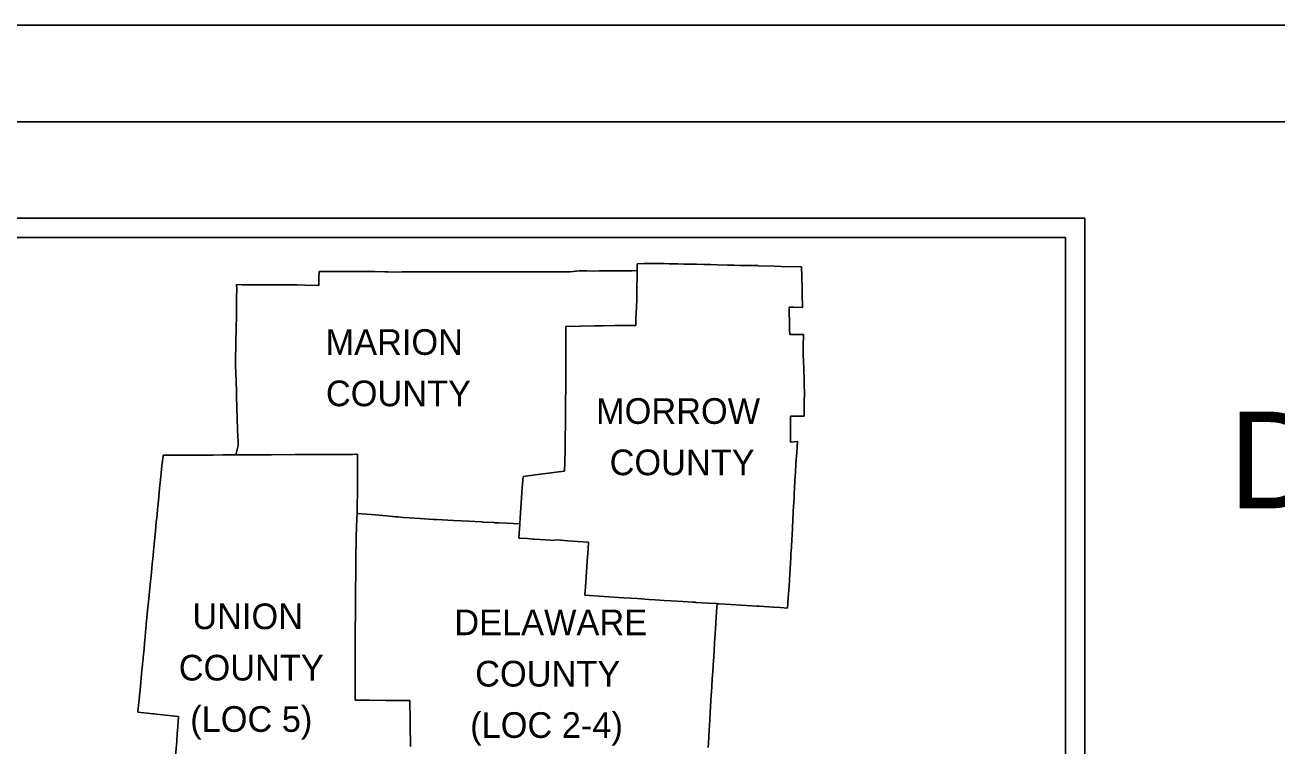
# Model space of a CAD drawing. Extents: x 0 to 34, y 0 to 22.
# Drawn here: x 3.52 to 9.99, y 18.27 to 22 of the extents above; entities that cross this region are included whole.
import ezdxf

# ---------------------------------------------------------------- set-up
doc = ezdxf.new("R2010")
doc.units = 0
for name, color, linetype in [('GM_X_County', 7, 'Continuous'), ('SH_Border', 7, 'Continuous'), ('SH_Cut_Line', 7, 'Continuous'), ('SH_Data', 7, 'Continuous'), ('SH_Text', 7, 'Continuous')]:
    doc.layers.add(name, color=color, linetype=linetype)

msp = doc.modelspace()

# ---------------------------------------------------------------- linework, layer by layer
at = {"layer": 'GM_X_County'}
for p, q in [((5.0405, 20.6879), (5.0411, 20.725)), ((5.0411, 20.725), (5.0621, 20.7251)), ((5.0621, 20.7251), (5.1848, 20.725)), ((5.1848, 20.725), (5.2501, 20.7247)), ((5.2501, 20.7247), (5.329, 20.7243)), ((5.329, 20.7243), (5.3818, 20.7231)), ((5.3818, 20.7231), (5.3901, 20.7232)), ((5.3901, 20.7232), (5.3993, 20.723)), ((5.3993, 20.723), (5.4521, 20.7223)), ((5.4521, 20.7223), (5.4693, 20.7224)), ((5.4693, 20.7224), (5.5416, 20.7227)), ((5.5416, 20.7227), (5.567, 20.7229)), ((5.567, 20.7229), (5.5697, 20.723)), ((5.5697, 20.723), (5.5794, 20.7231)), ((5.5794, 20.7231), (5.6115, 20.7233)), ((5.6115, 20.7233), (5.6401, 20.7234)), ((5.6401, 20.7234), (5.6827, 20.7237)), ((5.6827, 20.7237), (5.753, 20.724)), ((5.753, 20.724), (5.8235, 20.7233)), ((5.8235, 20.7233), (5.8261, 20.7233)), ((5.8261, 20.7233), (5.8298, 20.7232)), ((5.8298, 20.7232), (5.8419, 20.7232)), ((5.8419, 20.7232), (5.8941, 20.7231)), ((5.8941, 20.7231), (5.9122, 20.7229)), ((5.9122, 20.7229), (6.0406, 20.7231)), ((6.0406, 20.7231), (6.1476, 20.7233)), ((6.1476, 20.7233), (6.2484, 20.7238)), ((6.2484, 20.7238), (6.2963, 20.723)), ((6.2963, 20.723), (6.3143, 20.7226)), ((6.3143, 20.7226), (6.3191, 20.7226)), ((6.3191, 20.7226), (6.3236, 20.7228)), ((6.3236, 20.7228), (6.3375, 20.7237)), ((6.3375, 20.7237), (6.3545, 20.725)), ((6.3545, 20.725), (6.3662, 20.7259)), ((6.3662, 20.7259), (6.3728, 20.7263)), ((6.3728, 20.7263), (6.3872, 20.7275)), ((6.3872, 20.7275), (6.3891, 20.7276)), ((6.3891, 20.7276), (6.4254, 20.7277)), ((6.4254, 20.7277), (6.4621, 20.7274)), ((6.4621, 20.7274), (6.4892, 20.7279)), ((6.4892, 20.7279), (6.4913, 20.728)), ((6.4913, 20.728), (6.4973, 20.728)), ((6.4973, 20.728), (6.5516, 20.7282)), ((6.5516, 20.7282), (6.5752, 20.7283)), ((6.5752, 20.7283), (6.6354, 20.7289)), ((6.6354, 20.7289), (6.6595, 20.7292)), ((6.6595, 20.7292), (6.6856, 20.7295)), ((6.6856, 20.7295), (6.6853, 20.6951)), ((6.6856, 20.7295), (6.6866, 20.7654)), ((6.6866, 20.7654), (6.7195, 20.7656)), ((6.7195, 20.7656), (6.7729, 20.7658)), ((6.7729, 20.7658), (6.7945, 20.7658)), ((6.7945, 20.7658), (6.803, 20.7656)), ((6.803, 20.7656), (6.8079, 20.7658)), ((6.8079, 20.7658), (6.8254, 20.766)), ((6.8254, 20.766), (6.8515, 20.7651)), ((6.8515, 20.7651), (6.886, 20.7639)), ((6.886, 20.7639), (6.8953, 20.7638)), ((6.8953, 20.7638), (6.9269, 20.7633)), ((6.9269, 20.7633), (6.9307, 20.7631)), ((6.9307, 20.7631), (6.9473, 20.7629)), ((6.9473, 20.7629), (6.9532, 20.7628)), ((6.9532, 20.7628), (6.9634, 20.7628)), ((6.9634, 20.7628), (6.9922, 20.7622)), ((6.9922, 20.7622), (7.0299, 20.7614)), ((7.0299, 20.7614), (7.0649, 20.7604)), ((7.0649, 20.7604), (7.1, 20.7596)), ((7.1, 20.7596), (7.1524, 20.7582)), ((7.1524, 20.7582), (7.1695, 20.7575)), ((7.1695, 20.7575), (7.1866, 20.7571)), ((7.1866, 20.7571), (7.2147, 20.7565)), ((7.2147, 20.7565), (7.3093, 20.7565)), ((7.3093, 20.7565), (7.3093, 20.7542)), ((7.3093, 20.7542), (7.3951, 20.752)), ((7.3951, 20.752), (7.4302, 20.7511)), ((7.4302, 20.7511), (7.5362, 20.7483)), ((7.5362, 20.7483), (7.5371, 20.6992)), ((4.6151, 20.6558), (4.6152, 20.6569)), ((4.6151, 20.652), (4.6151, 20.6558)), ((4.6153, 20.6358), (4.6151, 20.652)), ((4.6152, 20.6569), (4.6438, 20.6567)), ((4.6438, 20.6567), (4.7179, 20.6562)), ((4.7179, 20.6562), (4.7573, 20.656)), ((4.7573, 20.656), (4.8279, 20.656)), ((4.8279, 20.656), (4.899, 20.6556)), ((4.899, 20.6556), (4.9257, 20.6554)), ((4.9257, 20.6554), (4.9685, 20.6545)), ((4.9685, 20.6545), (5.0394, 20.6529)), ((5.0394, 20.6529), (5.04, 20.6529)), ((5.04, 20.6537), (5.0405, 20.6879)), ((5.04, 20.6529), (5.04, 20.6537)), ((6.6853, 20.6951), (6.6847, 20.6432)), ((7.5371, 20.6992), (7.5389, 20.6325)), ((4.6149, 20.534), (4.6152, 20.5873)), ((4.6152, 20.5873), (4.6153, 20.6358)), ((6.6841, 20.5823), (6.6829, 20.5394)), ((6.6845, 20.6263), (6.6841, 20.5852)), ((6.6841, 20.5852), (6.6841, 20.5823)), ((6.6847, 20.6432), (6.6845, 20.6263)), ((7.5389, 20.6325), (7.5396, 20.6085)), ((7.5396, 20.6085), (7.5412, 20.5388)), ((4.6142, 20.4815), (4.6149, 20.534)), ((6.6828, 20.5379), (6.6796, 20.4842)), ((6.6829, 20.5394), (6.6828, 20.5379)), ((7.4947, 20.5397), (7.4719, 20.5401)), ((7.4719, 20.5401), (7.4724, 20.5242)), ((7.4724, 20.5242), (7.4722, 20.5102)), ((7.5412, 20.5388), (7.4947, 20.5397)), ((4.6134, 20.4465), (4.6142, 20.4815)), ((6.6796, 20.4842), (6.6794, 20.4454)), ((7.4722, 20.5102), (7.4722, 20.5091)), ((7.4722, 20.5091), (7.4731, 20.4672)), ((7.4731, 20.4672), (7.474, 20.4249)), ((4.6106, 20.3414), (4.6134, 20.4465)), ((6.3888, 20.4424), (6.3171, 20.441)), ((6.3171, 20.441), (6.3172, 20.4059)), ((6.3172, 20.4059), (6.3172, 20.3947)), ((6.3172, 20.3947), (6.3173, 20.3712)), ((6.3927, 20.4425), (6.3888, 20.4424)), ((6.4647, 20.4432), (6.3927, 20.4425)), ((6.4769, 20.4434), (6.4647, 20.4432)), ((6.482, 20.4435), (6.4769, 20.4434)), ((6.5063, 20.444), (6.482, 20.4435)), ((6.5685, 20.4447), (6.5063, 20.444)), ((6.603, 20.4451), (6.5685, 20.4447)), ((6.6383, 20.4454), (6.603, 20.4451)), ((6.6794, 20.4454), (6.6383, 20.4454)), ((7.474, 20.4249), (7.4745, 20.3989)), ((7.4745, 20.3989), (7.4952, 20.3991)), ((7.4952, 20.3991), (7.5454, 20.3989)), ((7.5454, 20.3989), (7.5444, 20.3365)), ((4.6101, 20.2718), (4.6106, 20.3414)), ((6.3173, 20.3435), (6.3172, 20.2998)), ((6.3173, 20.3712), (6.3173, 20.3435)), ((7.5444, 20.3365), (7.5443, 20.3345)), ((7.5443, 20.3345), (7.5443, 20.3204)), ((4.61, 20.2358), (4.6101, 20.2708)), ((4.6101, 20.2708), (4.6101, 20.2718)), ((6.3172, 20.2998), (6.317, 20.2299)), ((7.5443, 20.3204), (7.5444, 20.2979)), ((7.5444, 20.2979), (7.5459, 20.2576)), ((4.6104, 20.2048), (4.61, 20.2358)), ((4.6137, 20.1056), (4.6104, 20.2048)), ((6.317, 20.2299), (6.3168, 20.1568)), ((7.5459, 20.2576), (7.5473, 20.2239)), ((7.5473, 20.2239), (7.5487, 20.1629)), ((6.3168, 20.1568), (6.3153, 20.0187)), ((7.5487, 20.1629), (7.549, 20.153)), ((7.549, 20.153), (7.5507, 20.0826)), ((4.6143, 20.0864), (4.6137, 20.1056)), ((4.6146, 20.0742), (4.6143, 20.0864)), ((4.6147, 20.073), (4.6146, 20.0742)), ((4.6159, 20.0266), (4.6147, 20.073)), ((7.5499, 20.0717), (7.5496, 20.0678)), ((7.5496, 20.0678), (7.5496, 20.0631)), ((7.55, 20.0727), (7.5499, 20.0717)), ((7.5503, 20.0735), (7.55, 20.0727)), ((7.5506, 20.074), (7.5503, 20.0735)), ((7.5508, 20.079), (7.5506, 20.074)), ((7.5507, 20.0826), (7.5508, 20.079)), ((4.616, 20.0228), (4.6159, 20.0266)), ((4.6162, 20.0178), (4.616, 20.0228)), ((4.6179, 19.9678), (4.6162, 20.0178)), ((6.3153, 20.0187), (6.3146, 19.9478)), ((7.5496, 20.0597), (7.5495, 20.0116)), ((7.5495, 20.0116), (7.5497, 19.9808)), ((7.5496, 20.0631), (7.5496, 20.0597)), ((4.6203, 19.902), (4.6179, 19.9678)), ((6.3146, 19.9478), (6.3135, 19.8521)), ((7.4791, 19.945), (7.479, 19.9046)), ((7.5453, 19.9759), (7.4791, 19.9766)), ((7.4791, 19.9766), (7.4791, 19.9708)), ((7.4791, 19.9708), (7.4791, 19.945)), ((7.5497, 19.9759), (7.5453, 19.9759)), ((7.5497, 19.9808), (7.5497, 19.9759)), ((4.6225, 19.8473), (4.6203, 19.902)), ((7.479, 19.9046), (7.4788, 19.8413)), ((4.6114, 19.7761), (4.6234, 19.8253)), ((4.6234, 19.8253), (4.6225, 19.8473)), ((6.3128, 19.8072), (6.3116, 19.737)), ((6.3135, 19.8521), (6.3128, 19.8072)), ((7.4788, 19.8413), (7.5127, 19.8457)), ((7.5145, 19.8458), (7.5105, 19.7867)), ((7.5127, 19.8457), (7.5145, 19.8458)), ((4.2291, 19.7189), (4.2348, 19.7709)), ((4.2348, 19.7709), (4.2352, 19.7745)), ((4.2352, 19.7745), (4.2355, 19.7745)), ((4.2355, 19.7745), (4.3101, 19.7744)), ((4.3101, 19.7744), (4.3201, 19.7745)), ((4.3201, 19.7745), (4.4466, 19.7751)), ((4.4466, 19.7751), (4.4939, 19.7753)), ((4.4939, 19.7753), (4.5443, 19.7756)), ((4.5443, 19.7756), (4.6114, 19.7761)), ((4.6572, 19.7763), (4.6114, 19.7761)), ((4.7464, 19.7766), (4.6572, 19.7763)), ((4.7722, 19.7767), (4.7464, 19.7766)), ((4.7947, 19.7769), (4.7722, 19.7767)), ((4.9158, 19.7778), (4.7947, 19.7769)), ((4.9688, 19.778), (4.9158, 19.7778)), ((5.0125, 19.7781), (4.9688, 19.778)), ((5.085, 19.7785), (5.0125, 19.7781)), ((5.1554, 19.7788), (5.085, 19.7785)), ((5.2154, 19.779), (5.1554, 19.7788)), ((5.2346, 19.7791), (5.2154, 19.779)), ((5.2402, 19.7791), (5.2346, 19.7791)), ((5.2403, 19.7489), (5.2402, 19.7791)), ((5.2402, 19.7186), (5.2403, 19.7452)), ((5.2403, 19.7452), (5.2403, 19.7489)), ((7.5105, 19.7867), (7.5068, 19.7342)), ((4.2193, 19.6292), (4.2291, 19.7189)), ((5.2399, 19.6563), (5.2402, 19.7186)), ((6.2406, 19.6837), (6.1578, 19.6725)), ((6.2538, 19.6854), (6.2406, 19.6837)), ((6.2938, 19.6906), (6.2538, 19.6854)), ((6.3106, 19.6928), (6.2938, 19.6906)), ((6.3116, 19.737), (6.3106, 19.6928)), ((7.5038, 19.6809), (7.503, 19.6673)), ((7.5047, 19.697), (7.5038, 19.6809)), ((7.5059, 19.7185), (7.5047, 19.697)), ((7.5068, 19.7342), (7.5059, 19.7185)), ((4.2107, 19.5404), (4.2184, 19.6213)), ((4.2184, 19.6213), (4.2193, 19.6292)), ((5.2392, 19.5669), (5.2396, 19.6128)), ((5.2396, 19.6128), (5.2399, 19.6563)), ((6.0957, 19.6636), (6.0918, 19.6072)), ((6.1326, 19.6689), (6.0957, 19.6636)), ((6.1384, 19.6697), (6.1326, 19.6689)), ((6.1578, 19.6725), (6.1384, 19.6697)), ((7.503, 19.6673), (7.4982, 19.5761)), ((5.2387, 19.5275), (5.2392, 19.5669)), ((6.0918, 19.6072), (6.0864, 19.5285)), ((7.4968, 19.5568), (7.4952, 19.5252)), ((7.4982, 19.5761), (7.4968, 19.5568)), ((4.2036, 19.4675), (4.2062, 19.4936)), ((4.2062, 19.4936), (4.2107, 19.5404)), ((5.2376, 19.4736), (5.2383, 19.5069)), ((5.2383, 19.5069), (5.2387, 19.5275)), ((6.0864, 19.5285), (6.0811, 19.4514)), ((7.4948, 19.5152), (7.4884, 19.4028)), ((7.4952, 19.5252), (7.4948, 19.5152)), ((4.1954, 19.3831), (4.1998, 19.4294)), ((4.1998, 19.4294), (4.2017, 19.4482)), ((4.2017, 19.4482), (4.2036, 19.4675)), ((5.2339, 19.3538), (5.2364, 19.4466)), ((5.2364, 19.4466), (5.2365, 19.4529)), ((5.2365, 19.4529), (5.2376, 19.4736)), ((5.2376, 19.4736), (5.3126, 19.4675)), ((5.3126, 19.4675), (5.3905, 19.4609)), ((5.3905, 19.4609), (5.4384, 19.4564)), ((5.4384, 19.4564), (5.4467, 19.4555)), ((5.4467, 19.4555), (5.4485, 19.4552)), ((5.4485, 19.4552), (5.4774, 19.4526)), ((5.4774, 19.4526), (5.5631, 19.4467)), ((5.5631, 19.4467), (5.6333, 19.4427)), ((5.6333, 19.4427), (5.6494, 19.4423)), ((5.6494, 19.4423), (5.7358, 19.4364)), ((5.7358, 19.4364), (5.8157, 19.4328)), ((5.8157, 19.4328), (5.8793, 19.429)), ((5.8793, 19.429), (5.8884, 19.4285)), ((5.8884, 19.4285), (5.8912, 19.4283)), ((5.8912, 19.4283), (5.9457, 19.4256)), ((5.9457, 19.4256), (5.9494, 19.4255)), ((5.9494, 19.4255), (5.9579, 19.4251)), ((5.9579, 19.4251), (5.9644, 19.4247)), ((5.9644, 19.4247), (5.9711, 19.4243)), ((5.9711, 19.4243), (6.0105, 19.4222)), ((6.0105, 19.4222), (6.0789, 19.4187)), ((6.0789, 19.4187), (6.0739, 19.3459)), ((6.0811, 19.4514), (6.0789, 19.4187)), ((4.1919, 19.3474), (4.1954, 19.3831)), ((5.2338, 19.3517), (5.2339, 19.3538)), ((7.488, 19.3953), (7.4858, 19.3354)), ((7.4884, 19.4028), (7.488, 19.3953)), ((4.1853, 19.2794), (4.1919, 19.3474)), ((5.232, 19.2738), (5.2327, 19.3073)), ((5.2327, 19.3073), (5.2338, 19.3517)), ((6.0739, 19.3459), (6.1195, 19.3429)), ((6.1195, 19.3429), (6.146, 19.3409)), ((6.146, 19.3409), (6.1542, 19.3402)), ((6.1542, 19.3402), (6.2375, 19.3345)), ((6.2375, 19.3345), (6.2546, 19.3335)), ((6.2546, 19.3335), (6.255, 19.3369)), ((6.255, 19.3369), (6.2909, 19.3345)), ((6.2909, 19.3345), (6.3273, 19.3324)), ((6.3273, 19.3324), (6.3779, 19.3287)), ((6.3779, 19.3287), (6.4336, 19.3249)), ((6.4319, 19.2909), (6.4268, 19.224)), ((6.4336, 19.3249), (6.4319, 19.2909)), ((7.4858, 19.335), (7.4815, 19.2751)), ((7.4858, 19.3354), (7.4858, 19.335)), ((4.1786, 19.2114), (4.1829, 19.2554)), ((4.1829, 19.2554), (4.1853, 19.2794)), ((5.2313, 19.1726), (5.232, 19.2738)), ((6.4268, 19.224), (6.4197, 19.1184)), ((7.4796, 19.2456), (7.4729, 19.1318)), ((7.4807, 19.2633), (7.4796, 19.2456)), ((7.481, 19.268), (7.4807, 19.2633)), ((7.4815, 19.2751), (7.481, 19.268)), ((4.1726, 19.1505), (4.1745, 19.1699)), ((4.1745, 19.1699), (4.1786, 19.2114)), ((5.2305, 19.14), (5.2313, 19.1726)), ((4.159, 19.0138), (4.1678, 19.1053)), ((4.1678, 19.1053), (4.1726, 19.1505)), ((5.2302, 19.0808), (5.2303, 19.1006)), ((5.2303, 19.1006), (5.2305, 19.14)), ((6.4197, 19.1184), (6.4165, 19.0718)), ((7.4708, 19.0971), (7.4682, 19.0561)), ((7.4725, 19.1289), (7.4708, 19.0971)), ((7.4729, 19.1318), (7.4725, 19.1289)), ((5.229, 19.0331), (5.2302, 19.0808)), ((5.229, 19.0154), (5.229, 19.0331)), ((6.4155, 19.0558), (6.415, 19.0497)), ((6.415, 19.0497), (6.4398, 19.0488)), ((6.4165, 19.0718), (6.4155, 19.0558)), ((6.4398, 19.0488), (6.5888, 19.0388)), ((6.5888, 19.0388), (6.6174, 19.037)), ((6.6174, 19.037), (6.6855, 19.0326)), ((6.6855, 19.0326), (6.7462, 19.0286)), ((6.7462, 19.0286), (6.7791, 19.0269)), ((7.4671, 19.0382), (7.4654, 19.0097)), ((7.4682, 19.0561), (7.4671, 19.0382)), ((4.148, 18.8979), (4.155, 18.9711)), ((4.155, 18.9711), (4.1567, 18.9886)), ((4.1567, 18.9886), (4.159, 19.0138)), ((5.2291, 18.9673), (5.229, 19.0154)), ((5.229, 18.942), (5.2291, 18.9673)), ((6.7791, 19.0269), (6.8256, 19.0237)), ((6.8256, 19.0237), (6.8616, 19.0212)), ((6.8616, 19.0212), (6.922, 19.0176)), ((6.922, 19.0176), (6.9725, 19.0143)), ((6.9725, 19.0143), (6.9844, 19.0136)), ((6.9844, 19.0136), (6.989, 19.0133)), ((6.989, 19.0133), (7.0549, 19.0094)), ((7.0549, 19.0094), (7.0992, 19.0067)), ((7.0963, 18.9644), (7.0905, 18.8757)), ((7.0992, 19.0067), (7.0963, 18.9644)), ((7.1021, 19.0065), (7.0992, 19.0067)), ((7.1094, 19.0061), (7.1021, 19.0065)), ((7.1699, 19.0024), (7.1094, 19.0061)), ((7.2243, 18.9992), (7.1699, 19.0024)), ((7.3036, 18.9942), (7.2243, 18.9992)), ((7.3161, 18.9932), (7.3036, 18.9942)), ((7.3901, 18.9884), (7.3161, 18.9932)), ((7.4268, 18.9861), (7.3901, 18.9884)), ((7.4638, 18.9838), (7.4268, 18.9861)), ((7.4654, 19.0097), (7.4638, 18.9838)), ((5.2283, 18.8988), (5.2286, 18.9118)), ((5.2286, 18.9118), (5.2288, 18.9137)), ((5.2288, 18.9137), (5.229, 18.942)), ((4.1405, 18.8162), (4.148, 18.8979)), ((5.2277, 18.6909), (5.2283, 18.8529)), ((5.2283, 18.8529), (5.2283, 18.8988)), ((7.0905, 18.8757), (7.0857, 18.8037)), ((4.1337, 18.7446), (4.1363, 18.7719)), ((4.1363, 18.7719), (4.1393, 18.8033)), ((4.1393, 18.8033), (4.1405, 18.8162)), ((7.0856, 18.801), (7.0814, 18.7337)), ((7.0857, 18.8024), (7.0856, 18.801)), ((7.0857, 18.8037), (7.0857, 18.8024)), ((4.1297, 18.7031), (4.1337, 18.7446)), ((7.0796, 18.709), (7.0789, 18.6896)), ((7.0814, 18.7337), (7.0796, 18.709)), ((4.1174, 18.5774), (4.1239, 18.644)), ((4.1239, 18.644), (4.1287, 18.6925)), ((4.1287, 18.6925), (4.1291, 18.6967)), ((4.1291, 18.6967), (4.1297, 18.7031)), ((5.2285, 18.6034), (5.2277, 18.6909)), ((7.0764, 18.6552), (7.0743, 18.6171)), ((7.077, 18.6635), (7.0764, 18.6552)), ((7.0779, 18.6768), (7.077, 18.6635)), ((7.0786, 18.6894), (7.0779, 18.6768)), ((7.0789, 18.6896), (7.0786, 18.6894)), ((4.1076, 18.479), (4.1174, 18.5774)), ((5.2284, 18.5367), (5.2285, 18.6034)), ((7.0717, 18.5778), (7.0702, 18.5525)), ((7.0743, 18.6171), (7.0717, 18.5778)), ((5.2287, 18.5076), (5.2284, 18.5367)), ((7.0702, 18.5525), (7.0673, 18.5072)), ((4.1043, 18.4455), (4.1046, 18.4478)), ((4.1046, 18.4478), (4.1076, 18.479)), ((5.2338, 18.5075), (5.2287, 18.5076)), ((5.2638, 18.5073), (5.2338, 18.5075)), ((5.2774, 18.507), (5.2638, 18.5073)), ((5.3044, 18.5069), (5.2774, 18.507)), ((5.3875, 18.5059), (5.3044, 18.5069)), ((5.4364, 18.5055), (5.3875, 18.5059)), ((5.493, 18.5048), (5.4364, 18.5055)), ((5.5113, 18.5048), (5.493, 18.5048)), ((5.5131, 18.3987), (5.5113, 18.5048)), ((7.0671, 18.5057), (7.0637, 18.442)), ((7.0673, 18.5072), (7.0671, 18.5057)), ((4.1836, 18.4371), (4.1043, 18.4455)), ((4.1888, 18.4365), (4.1836, 18.4371)), ((4.1989, 18.4355), (4.1888, 18.4365)), ((4.3146, 18.4234), (4.1989, 18.4355)), ((4.309, 18.3461), (4.3146, 18.4234)), ((5.5131, 18.3699), (5.5131, 18.3987)), ((7.0616, 18.4073), (7.0567, 18.3217)), ((7.0637, 18.442), (7.0616, 18.4073)), ((4.3052, 18.2938), (4.3085, 18.3389)), ((4.3085, 18.3389), (4.309, 18.3461)), ((5.5136, 18.281), (5.5131, 18.3699)), ((7.0567, 18.3217), (7.0564, 18.3154)), ((4.2999, 18.2208), (4.3052, 18.2938)), ((5.5143, 18.2683), (5.5136, 18.281)), ((7.0546, 18.2864), (7.0532, 18.2617)), ((7.0564, 18.3154), (7.0546, 18.2864))]:
    msp.add_line(p, q, dxfattribs=at)
at = {"layer": 'SH_Border'}
msp.add_lwpolyline([(1.5, 21.5), (33.5, 21.5), (33.5, 0.5), (1.5, 0.5)], close=True, dxfattribs=at)
at = {"layer": 'SH_Cut_Line'}
msp.add_lwpolyline([(0, 0), (34, 0), (34, 22), (0, 22)], close=True, dxfattribs=at)
at = {"layer": 'SH_Data'}
for p, q in [((2, 21), (9, 21)), ((9, 21), (9, 14)), ((2.1, 20.9), (8.9, 20.9)), ((8.9, 20.9), (8.9, 14.1))]:
    msp.add_line(p, q, dxfattribs=at)

# ---------------------------------------------------------------- texts
for s, p in [('MARION', (5.0747, 20.2936)), ('COUNTY', (5.0767, 20.028)), ('MORROW', (6.4731, 19.9367)), ('COUNTY', (6.5433, 19.6711)), ('UNION', (4.386, 18.8747)), ('DELAWARE', (5.7404, 18.8435)), ('COUNTY', (4.3158, 18.609)), ('COUNTY', (5.8483, 18.5778)), ('(LOC 5)', (4.3751, 18.3434)), ('(LOC 2-4)', (5.8225, 18.3122))]:
    msp.add_text(s, height=0.13282, dxfattribs=at).set_placement(p)
at = {"layer": 'SH_Text'}
msp.add_text('DEPARTMENT OF TRANSPORTATION', height=0.5, dxfattribs=at).set_placement((9.7466, 19.5))

doc.saveas('drawing.dxf')
